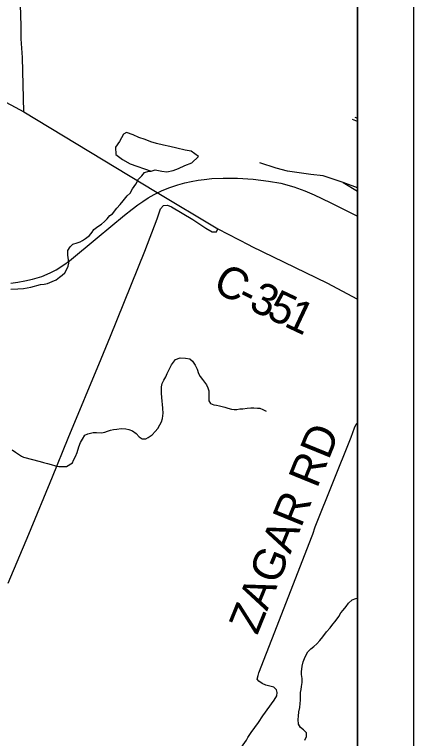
# Model space of a CAD drawing. Extents: x 0 to 34, y 0 to 22.
# Drawn here: x 8.286 to 9, y 15.409 to 16.702 of the extents above; entities that cross this region are included whole.
import ezdxf

# ---------------------------------------------------------------- set-up
doc = ezdxf.new("R2010")
doc.units = 0
for name, color, linetype in [('GM_X_Corporation', 7, 'Continuous'), ('GM_X_County_Road', 7, 'Continuous'), ('GM_X_County_Road_Text', 7, 'Continuous'), ('GM_X_Minor_Lake', 7, 'Continuous'), ('GM_X_Minor_River', 7, 'Continuous'), ('GM_X_Rail_Line', 7, 'Continuous'), ('GM_X_Township_Road', 7, 'Continuous'), ('GM_X_Township_Road_Text', 7, 'Continuous'), ('SH_Data', 7, 'Continuous')]:
    doc.layers.add(name, color=color, linetype=linetype)

msp = doc.modelspace()

# ---------------------------------------------------------------- linework, layer by layer
at = {"layer": 'GM_X_Corporation'}
msp.add_lwpolyline([(8.9, 15.0205), (8.9, 18.9286)], dxfattribs=at)
at = {"layer": 'GM_X_County_Road'}
for points in [[(8.3032, 16.5286), (8.3009, 16.6257), (8.2982, 16.6588), (8.2982, 16.6817), (8.2973, 16.72), (8.3004, 16.7543), (8.307, 16.775), (8.3158, 16.7917), (8.3268, 16.8063), (8.3436, 16.8243), (8.3581, 16.8393), (8.3858, 16.8648), (8.4462, 16.9102)], [(7.6643, 16.8192), (7.7102, 16.793), (7.7437, 16.7732), (7.7803, 16.752), (7.8095, 16.7352), (7.8616, 16.7151), (7.9117, 16.6946), (7.9564, 16.6765), (7.9912, 16.6622), (8.0435, 16.6435), (8.0693, 16.6339), (8.1144, 16.6156), (8.158, 16.5998), (8.1895, 16.5855), (8.2066, 16.5786), (8.2241, 16.5696), (8.2549, 16.5543), (8.3032, 16.5286), (8.5388, 16.3863), (8.6502, 16.3199), (8.7056, 16.2911)], [(8.7056, 16.2911), (8.7111, 16.2882), (8.8451, 16.2229), (8.9, 16.1942)]]:
    msp.add_lwpolyline(points, dxfattribs=at)
at = {"layer": 'GM_X_Minor_Lake'}
for points in [[(8.4867, 16.4914), (8.4813, 16.4885), (8.4742, 16.4757), (8.4672, 16.4656), (8.4677, 16.4526), (8.4797, 16.4437), (8.4932, 16.4359), (8.5309, 16.4229)], [(8.5309, 16.4229), (8.5377, 16.4251), (8.5496, 16.4224), (8.559, 16.4214), (8.5701, 16.4239), (8.5797, 16.4275), (8.5911, 16.433), (8.6034, 16.4377), (8.6154, 16.4489), (8.6026, 16.4586), (8.5913, 16.4603), (8.5769, 16.4636), (8.5644, 16.4665), (8.5527, 16.469), (8.5402, 16.4722), (8.5304, 16.4751), (8.5202, 16.479), (8.5085, 16.483), (8.4984, 16.4874), (8.4867, 16.4914)]]:
    msp.add_lwpolyline(points, dxfattribs=at)
at = {"layer": 'GM_X_Minor_River'}
for points in [[(8.3154, 16.2156), (8.3328, 16.2199), (8.3393, 16.2209), (8.3455, 16.2222), (8.354, 16.2258), (8.3609, 16.2286), (8.3667, 16.233), (8.3714, 16.2367), (8.3761, 16.2411), (8.3793, 16.2463), (8.3825, 16.2531), (8.3834, 16.258), (8.3829, 16.2645), (8.3815, 16.2725), (8.3818, 16.2809), (8.3858, 16.2872), (8.3909, 16.292), (8.3986, 16.2949), (8.4036, 16.2966), (8.4082, 16.2988), (8.4136, 16.3024), (8.4202, 16.3076), (8.425, 16.3139), (8.4282, 16.3184), (8.4352, 16.3239), (8.4418, 16.3282), (8.4472, 16.333), (8.4523, 16.3374), (8.4571, 16.3434), (8.4617, 16.3467), (8.4692, 16.3567), (8.4751, 16.363), (8.4807, 16.3697), (8.4881, 16.3787), (8.4932, 16.3835), (8.4976, 16.3913), (8.5032, 16.3995), (8.5084, 16.4081), (8.5139, 16.4144), (8.5186, 16.42), (8.5267, 16.4224), (8.5309, 16.4229)], [(8.2796, 16.212), (8.2925, 16.2126), (8.3024, 16.2132), (8.3154, 16.2156)], [(8.3027, 15.9115), (8.3321, 15.9041), (8.3385, 15.9024), (8.3453, 15.9003), (8.3521, 15.8986), (8.3597, 15.8961), (8.3654, 15.8951), (8.373, 15.8949), (8.3795, 15.8951), (8.3899, 15.9016), (8.392, 15.9065), (8.3956, 15.9129), (8.3984, 15.92), (8.4014, 15.9302), (8.4046, 15.9377), (8.4082, 15.9441), (8.4122, 15.9508), (8.4173, 15.9537), (8.4273, 15.9561), (8.4333, 15.9556), (8.4421, 15.9553), (8.4478, 15.9563), (8.4525, 15.9581), (8.4579, 15.9602), (8.4636, 15.9615), (8.4693, 15.9621), (8.477, 15.9631), (8.4854, 15.9624), (8.491, 15.9611), (8.4975, 15.959), (8.5042, 15.9539), (8.5094, 15.9484), (8.5146, 15.9448), (8.521, 15.9443), (8.5257, 15.9472), (8.5327, 15.9519), (8.5382, 15.9579), (8.5429, 15.963), (8.5465, 15.9694), (8.5493, 15.975), (8.551, 15.9811), (8.5524, 15.9902), (8.5519, 15.9989), (8.551, 16.0062), (8.5504, 16.0115), (8.5498, 16.0192), (8.5492, 16.0256), (8.549, 16.0317), (8.5492, 16.0374), (8.5505, 16.0435), (8.5533, 16.0491), (8.5569, 16.0555), (8.5594, 16.0615), (8.5634, 16.0694), (8.567, 16.0769), (8.5706, 16.0817), (8.5745, 16.0862), (8.5826, 16.089), (8.5921, 16.0887), (8.5997, 16.0874), (8.6049, 16.0834), (8.6097, 16.076), (8.6133, 16.0687), (8.6157, 16.061), (8.6183, 16.056), (8.6223, 16.0505), (8.626, 16.0459), (8.6297, 16.0408), (8.6322, 16.0358), (8.6339, 16.03), (8.6338, 16.0251), (8.634, 16.0198), (8.6342, 16.0125), (8.6371, 16.0075), (8.6428, 16.0054), (8.6477, 16.0045), (8.653, 16.0032), (8.6579, 16.0023), (8.6625, 16.0011), (8.6681, 15.9994), (8.6746, 15.9977), (8.6795, 15.9968), (8.6841, 15.997), (8.6891, 15.998), (8.6948, 15.9982), (8.7024, 15.9995), (8.7089, 15.9997), (8.7143, 15.9999), (8.7207, 15.9994), (8.7253, 15.9992), (8.7306, 15.9972), (8.7362, 15.994)], [(8.2823, 15.9248), (8.288, 15.9205), (8.2951, 15.9158), (8.2989, 15.9135), (8.3027, 15.9115)], [(8.8053, 15.4065), (8.8085, 15.4128), (8.8083, 15.4193), (8.8035, 15.4247), (8.7979, 15.4291), (8.7942, 15.4349), (8.7937, 15.4432), (8.7942, 15.4493), (8.7948, 15.4569), (8.7965, 15.4645), (8.7971, 15.4717), (8.7976, 15.4777), (8.7979, 15.4914), (8.7988, 15.4967), (8.7994, 15.5024), (8.8007, 15.5092), (8.8008, 15.5164), (8.7999, 15.5237), (8.7996, 15.5286), (8.8006, 15.5385), (8.8024, 15.5464), (8.8064, 15.5551), (8.8108, 15.5641), (8.8163, 15.5696), (8.8217, 15.5737), (8.8271, 15.5781), (8.8323, 15.5844), (8.8378, 15.5911), (8.8444, 15.5997), (8.8511, 15.6071), (8.8558, 15.6135), (8.8601, 15.6183), (8.8661, 15.6273), (8.8701, 15.634), (8.8744, 15.6388), (8.8798, 15.6452), (8.8838, 15.6508), (8.8904, 15.6571), (8.897, 15.6596), (8.9, 15.6601)]]:
    msp.add_lwpolyline(points, dxfattribs=at)
at = {"layer": 'GM_X_Rail_Line'}
for p, q in [((8.9, 16.5116), (8.891, 16.5147)), ((8.8949, 16.5188), (8.9, 16.517)), ((8.9, 16.3931), (8.8744, 16.4021))]:
    msp.add_line(p, q, dxfattribs=at)
for points in [[(8.8744, 16.4021), (8.8708, 16.4034), (8.8384, 16.4144), (8.8161, 16.4167), (8.7743, 16.4229), (8.7543, 16.428), (8.7254, 16.4375)], [(8.2799, 16.2226), (8.2925, 16.2243), (8.305, 16.2265), (8.3187, 16.2295), (8.3351, 16.2346), (8.35, 16.2409), (8.361, 16.2465), (8.3745, 16.2552), (8.3846, 16.2623), (8.4342, 16.3033), (8.4833, 16.3442), (8.4966, 16.3548), (8.5067, 16.3622), (8.516, 16.3685), (8.5256, 16.3749), (8.536, 16.3808), (8.5506, 16.388), (8.5643, 16.3933), (8.5787, 16.3981), (8.591, 16.4015), (8.6022, 16.4039), (8.615, 16.4063), (8.6253, 16.408), (8.6395, 16.4095), (8.6594, 16.4103), (8.6849, 16.4102), (8.7131, 16.4086), (8.7406, 16.4049), (8.7626, 16.4011), (8.7862, 16.3946), (8.8053, 16.3874), (8.8224, 16.3805), (8.8507, 16.3667), (8.9, 16.3425)], [(8.8744, 16.4021), (8.8996, 16.3869), (8.9, 16.3867)]]:
    msp.add_lwpolyline(points, dxfattribs=at)
at = {"layer": 'GM_X_Township_Road'}
for points in [[(8.2752, 15.6869), (8.3119, 15.7744), (8.3541, 15.8765), (8.3826, 15.9455), (8.4411, 16.0875), (8.4579, 16.1277), (8.5195, 16.2798), (8.5413, 16.3373), (8.5477, 16.3553), (8.5529, 16.3615), (8.5597, 16.3617), (8.567, 16.3587), (8.605, 16.3364), (8.6285, 16.3211), (8.6401, 16.3142), (8.6475, 16.3144), (8.6502, 16.3199)], [(8.8197, 15.774), (8.8243, 15.7871), (8.8884, 15.9476), (8.8947, 15.9644), (8.8976, 15.9706), (8.9, 15.9733)], [(8.7221, 15.522), (8.7234, 15.5266), (8.7604, 15.6213), (8.8177, 15.7684), (8.8197, 15.774)], [(8.7038, 15.4108), (8.7097, 15.42), (8.7225, 15.4377), (8.7305, 15.4499), (8.7505, 15.4776), (8.7553, 15.4856), (8.7564, 15.4916), (8.755, 15.4961), (8.7499, 15.5007), (8.736, 15.5046), (8.7291, 15.5078), (8.7231, 15.5115), (8.7202, 15.5155), (8.7221, 15.522)], [(8.5882, 15.247), (8.5893, 15.2487), (8.7011, 15.4066), (8.7038, 15.4108)]]:
    msp.add_lwpolyline(points, dxfattribs=at)
at = {"layer": 'SH_Data'}
for p, q in [((9, 21), (9, 14)), ((8.9, 20.9), (8.9, 14.1))]:
    msp.add_line(p, q, dxfattribs=at)

# ---------------------------------------------------------------- texts
at = {"layer": 'GM_X_County_Road_Text'}
for s, rotation, p in [('C', 331.3033, (8.6381, 16.2112)), ('3', 334.4324, (8.7031, 16.1769)), ('-', 333.9249, (8.6816, 16.1874)), ('5', 334.6481, (8.7348, 16.1617)), ('1', 334.6889, (8.7665, 16.1467))]:
    msp.add_text(s, height=0.0568, rotation=rotation, dxfattribs=at).set_placement(p)
at = {"layer": 'GM_X_Township_Road_Text'}
msp.add_text('ZAGAR RD', height=0.05682, rotation=67.8241, dxfattribs=at).set_placement((8.7205, 15.5927))

doc.saveas('drawing.dxf')
